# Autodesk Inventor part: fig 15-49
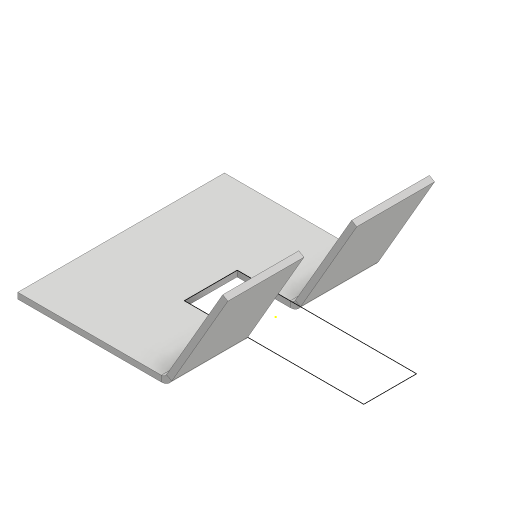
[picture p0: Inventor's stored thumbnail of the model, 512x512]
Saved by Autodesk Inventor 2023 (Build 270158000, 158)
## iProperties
Created: 2015-07
Part Number: fig 15-49
Material: Generic
Document SubType Name: Sheet Metal
Designer: Sandeep
Density: 1 g/cm^3
Sheet Metal Rule: Default_mm
Appearance: Default
Author: Sandeep
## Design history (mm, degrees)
node "Face1"
  sketch "Sketch1"
    geometry: L1 (-12.609, 8.313)-(0, 8.313); L2 (0, 8.313)-(0, -9.006); L3 (0, -9.006)-(-12.609, -9.006); L4 (-12.609, -9.006)-(-12.609, 8.313); 1 further point
    constraints: 8 end point, 2 parallel, 1 horizontal, 1 perpendicular
node "Flange1"
sketch "Sketch3"
  geometry: L1 (9.998, 1.795)-(-5.034, 1.795); L2 (-5.034, 1.795)-(-5.034, -2.633); L3 (-5.034, -2.633)-(9.998, -2.633); L4 (9.998, -2.633)-(9.998, 1.795); 1 further point
  constraints: 8 end point, 2 parallel, 1 horizontal, 1 perpendicular
cut "Cut1" sketch "Sketch3" dims "d11" = 0.5 (= Thickness), "d12" = 0
body "Solid1"
face "Plate1" dims "d13" = 0.5 (= Thickness)
sketch "Sketch2"
  geometry: L1 (0, 10)-(-17.319, 10); L2 (-17.319, 10)-(-17.319, 0); 1 other entity
  constraints: 4 end point, 4 other
face "Plate2" dims "d1" = 0.5 (= BendReliefWidth), "d2" = 0.25 (= BendReliefDepth), "d3" = 1 (= MinimumRemnant), "d4" = 0.5 (= BendRadius), "d5" = 10, "d6" = 60 deg, "d7" = 0.5 (= BendRadius), "d8" = 2 (= CornerReliefSize), "d9" = 0.5 (= GapSize), "d10" = 0.5 (= JacobiRadiusSize), "d13" = 0.5 (= Thickness), "SeamGap" = 0.01
bend "Bend1" dims "d1" = 0.5 (= BendReliefWidth), "d2" = 0.25 (= BendReliefDepth), "d3" = 1 (= MinimumRemnant), "d4" = 0.5 (= BendRadius), "d5" = 10, "d6" = 60 deg, "d7" = 0.5 (= BendRadius), "d13" = 0.5 (= Thickness), "SeamGap" = 0.01
feature "Corner1" dims "d5" = 10, "d6" = 60 deg, "d8" = 2 (= CornerReliefSize), "d9" = 0.5 (= GapSize), "d10" = 0.5 (= JacobiRadiusSize)
other parameters: "Thickness" = 0.5, "BendRadius" = 0.5 (= Thickness), "BendReliefWidth" = 0.5 (= Thickness), "BendReliefDepth" = 0.25 (= 0.5 x Thickness), "CornerReliefSize" = 2 (= 4 x Thickness), "MinimumRemnant" = 1 (= 2 x Thickness), "TransitionRadius" = 0.5 (= BendRadius), "JacobiRadiusSize" = 0.5 (= BendRadius), "GapSize" = 0.5 (= Thickness), "d0" = 0.5 (= BendRadius)
